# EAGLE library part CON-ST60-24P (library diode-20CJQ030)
Hirose's ST60-24P ST-Series 24pol Overview: Developed as external input/output connectors for the portable and mobile devices used in consumer markets. As such, the connectors incorporate features required to assure reliable electrical and mechanical performance under extreme and unpredictable conditions. Features 1. Strong locking mechanism To assure continuous reliability of the connection in an unpredictable consumer environment, mated connectors will withstand pull force of 49N max. applied in any direction. 2. Prevention against reversed or angle insertion Multiple polarization keys will not allow incorrect insertion of the mating plug. In addition, contacts will not be damaged when the user attempts to insert only the corner of the mating plug. 3. Small size and low profile Contact pitch of 0.5 mm and utilization of state-of-the-art manufacturing technologies has produced receptacle height of 3 mm above the board and maximum thickness of the plug of only 7 mm. 4. EMI protection Built-in ground continuity features and EMI shielding assure interference free performance. 5. Wide variety of contact positions and mounting styles Standard, reverse, vertical and cradle mountings, as well as utilization of variety of cables and conductors assure application of this connector in diversified applications. Applications: Digital Still Cameras, Personal Digital Assistance, Notebook computers, Cellular phones, Portable readers, Mobile recorders and any mobile or portable device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
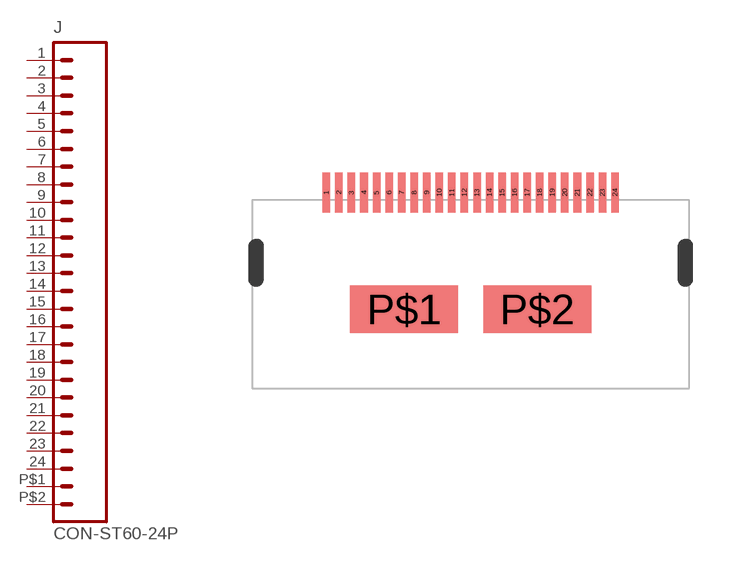
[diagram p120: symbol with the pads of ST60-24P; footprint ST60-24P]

Designator prefix J

## CON-ST60-24P  [ST60-24P]
1  1  pas
2  2  pas
3  3  pas
4  4  pas
5  5  pas
6  6  pas
7  7  pas
8  8  pas
9  9  pas
10  10  pas
11  11  pas
12  12  pas
13  13  pas
14  14  pas
15  15  pas
16  16  pas
17  17  pas
18  18  pas
19  19  pas
20  20  pas
21  21  pas
22  22  pas
23  23  pas
24  24  pas
P$1  25  pas
P$2  26  pas

## Footprint ST60-24P (pad centres in mm)
Hirose's ST60-24P ST-Series 24pol Overview: Developed as external input/output connectors for the portable and mobile devices used in consumer markets. As such, the connectors incorporate features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
smd 0.3 x 1.6: 1 -5.75,2.8; 2 -5.25,2.8; 3 -4.75,2.8; 4 -4.25,2.8; 5 -3.75,2.8; 6 -3.25,2.8; 7 -2.75,2.8; 8 -2.25,2.8; 9 -1.75,2.8; 10 -1.25,2.8; 11 -0.75,2.8; 12 -0.25,2.8; 13 0.25,2.8; 14 0.75,2.8; 15 1.25,2.8; 16 1.75,2.8; 17 2.25,2.8; 18 2.75,2.8; 19 3.25,2.8; 20 3.75,2.8; 21 4.25,2.8; 22 4.75,2.8; 23 5.25,2.8; 24 5.75,2.8
smd 4.3 x 1.9: P$1 -2.65,-1.85; P$2 2.65,-1.85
